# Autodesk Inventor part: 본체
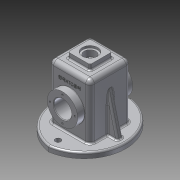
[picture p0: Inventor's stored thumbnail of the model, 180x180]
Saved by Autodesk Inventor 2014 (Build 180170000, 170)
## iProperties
Created: 2017-07
Part Number: 본체
Material: 알루미늄 6061
Document SubType Name: Modeling
Designer: user
Mass: 925.928 g
Surface Area: 965.8 cm^2
Volume: 341.671 cm^3
Density: 2.71 g/cm^3
Appearance: 알루미늄 - 평지
Author: user
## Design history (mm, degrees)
sketch "스케치1"
  geometry: L1 (-37, -37)-(37, -37); L2 (37, -37)-(37, 37); L3 (37, 37)-(-37, 37); L4 (-37, 37)-(-37, -37); L5 (-37, -37)-(37, 37); L6 (37, -37)-(-37, 37); 1 further point
  constraints: 12 end point, 2 midpoint, 2 parallel, 1 horizontal, 1 perpendicular
  dimensions: "d0" = 74 distance of L1.start L1.end; "d1" = 74 distance of L1.end L2.end
extrude "돌출1" new body sketch "스케치1" stored distance "d2" = 90; taper "d3" = 0 deg
node "작업 평면1"
sketch "스케치2"
  geometry: L1 (-75, -65)-(75, -65); L2 (75, -65)-(75, 65); L3 (75, 65)-(-75, 65); L4 (-75, 65)-(-75, -65); L5 (-75, -65)-(75, 65); L6 (75, -65)-(-75, 65); 1 further point
  constraints: 12 end point, 2 midpoint, 2 parallel, 1 horizontal, 1 perpendicular
  dimensions: "d5" = 150 distance of L2.end L3.end; "d6" = 130 distance of L3.end L1.start
extrude "돌출2" join sketch "스케치2" stored distance "d7" = 90; taper "d8" = 0 deg
sketch "스케치5"
  geometry: L1 (0, 0)-(0, 130) reference; L2 (150, 0)-(0, 0) reference; L3 (150, 130)-(150, 0) reference; L4 (0, 130)-(150, 130) reference; L5 (0, 130)-(0, 0) reference; L6 (0, 65)-(150, 65); A1 r 75.769 centre (75, 54.231) between (150, 65) and (0, 65); A2 r 75.769 centre (75, 75.769) between (0, 65) and (150, 65); 1 further point
  constraints: 4 point on circle, 2 centre point, 2 end point, 2 midpoint, 1 perpendicular, 1 symmetric about line, 1 other
  dimensions: "d29" = 130 distance of L1.start L1.end (derived)
extrude "돌출5" cut sketch "스케치5" stored distance "d15" = 13; taper "d16" = 0 deg
sketch "스케치7"
  geometry: 1 further point
sketch "스케치8"
  geometry: L1 (-37, -37)-(37, -37); L2 (37, -37)-(37, 37); L3 (37, 37)-(-37, 37); L4 (-37, 37)-(-37, -37); L5 (-37, -37)-(37, 37); L6 (37, -37)-(-37, 37); 1 further point
  constraints: 12 end point, 2 midpoint, 2 parallel, 1 horizontal, 1 perpendicular
extrude "돌출6" join sketch "스케치8" distance "d20" = 10; taper "d21" = 0 deg
sketch "스케치12"
  geometry: 1 further point
sketch "스케치13"
  geometry: C1 r 27.5 at (45, 37); 1 further point
  constraints: 1 centre point, 1 coincident
  dimensions: "d30" = 55 diameter of C1
extrude "돌출9" join sketch "스케치13" distance "d31" = 13; taper "d32" = 0 deg
sketch "스케치14"
  geometry: C1 r 27.5 at (-45, 37); 1 further point
  constraints: 1 centre point, 1 coincident
  dimensions: "d33" = 55 diameter of C1
extrude "돌출10" join sketch "스케치14" distance "d34" = 13; taper "d35" = 0 deg
sketch "스케치15"
  geometry: L1 (65, -45)-(-65, -45) reference; L2 (-65, -45)-(-55, -45); L3 (0, -45)-(-65, -45) reference; L4 (-65, -45)-(-65, 69.043); L5 (-55, -45)-(-32.5, 45.243); L6 (-55, -45)-(-32.5, -45); L7 (-32.5, -45)-(-55, -45); L8 (-55, -45)-(-32.5, -45); L9 (-37, 55)-(-37, -45) reference; L10 (37, 55)-(-37, 55) reference; L11 (37, -45)-(37, 55) reference; L12 (-37, -45)-(37, -45) reference; L13 (-32.5, 45.243)-(-32.5, -45); L14 (-37, 55)-(-37, -45) reference; L15 (-32.5, -45)-(-55, -45); C1 r 27.5 at (0, 0) reference; 1 further point
  constraints: 16 end point, 4 collinear, 1 midpoint, 1 parallel, 1 perpendicular, 1 point on line
  dimensions: "d36" = 10 distance of L1.end L2.end; "d37" = 14 deg angle of L5 L4
  node "투영된 루프1"
sketch "스케치16"
  geometry: 1 further point
extrude "돌출11" join sketch "스케치15" stored distance "d38" = 10; taper "d39" = 0 deg
sketch "스케치17"
  geometry: L1 (-20, -20)-(20, -20); L2 (20, -20)-(20, 20); L3 (20, 20)-(-20, 20); L4 (-20, 20)-(-20, -20); L5 (-20, -20)-(20, 20); L6 (20, -20)-(-20, 20); 1 further point
  constraints: 12 end point, 2 midpoint, 2 parallel, 1 horizontal, 1 perpendicular
  dimensions: "d40" = 40 distance of L3.end L2.end; "d41" = 40 distance of L2.end L1.end
extrude "돌출12" join sketch "스케치17" distance "d42" = 10; taper "d43" = 0 deg
sketch "스케치18"
  geometry: L1 (-50, 27.5)-(-50, -27.5) reference; L2 (-50, 0)-(50, 0); L3 (50, -27.5)-(50, 27.5) reference; L4 (-50, 0)-(-50, 16); L5 (-50, 16)-(-25, 16); L6 (-37, -45)-(-37, 55) reference; L7 (-25, 16)-(-25, 20.5); L8 (-25, 20.5)-(-32, 27.5); L9 (-32, 27.5)-(-32, 50); L10 (-32, 50)-(32, 50); L11 (32, 50)-(32, 27.5); L12 (32, 27.5)-(25, 20.5); L13 (25, 20.5)-(25, 16); L14 (25, 16)-(50, 16); L15 (37, 55)-(-37, 55) reference; L16 (0, 50)-(0, -55); L17 (-75, -55)-(75, -55) reference; L18 (-32, -27.5)-(-32, -50); L19 (-25, -20.5)-(-32, -27.5); L20 (32, -50)-(32, -27.5); L21 (32, -27.5)-(25, -20.5); L22 (25, -20.5)-(25, -16); L23 (25, -16)-(50, -16); L24 (-50, -16)-(-25, -16); L25 (-50, -27.5)-(-50, 27.5); L26 (-25, -20.5)-(-25, -16); L27 (32, -50)-(32, -55); L28 (-32, -50)-(-32, -55); L29 (-25, 16)-(-25, -16); L30 (25, 16)-(25, -16); L31 (-32, -55)-(32, -55); L32 (50, 16)-(50, -16); 1 further point
  constraints: 54 end point, 12 symmetric about line, 7 parallel, 7 perpendicular, 5 point on line, 4 midpoint, 1 collinear
  dimensions: "d44" = 16 distance of L2.start L4.end; "d45" = 5 distance between parallel lines of L10 L15; "d46" = 7 distance between parallel lines of L11 L13; "d47" = 7 distance between parallel lines of L9 L7; "d48" = 55 diameter of L8.end L2; "d49" = 55 diameter of L11.end L2; "d50" = 32 diameter of L14 L2; "d51" = 135 deg angle of L9 L8; "d52" = 135 deg angle of L11 L12 (derived); "d53" = 64 distance of L9.end L10.end; "d54" = 25 distance of L4.end L5.end
extrude "돌출13" cut sketch "스케치18" stored distance "d55" = 64; taper "d56" = 0 deg
sketch "스케치19"
  geometry: C1 r 27.5 at (0, 0) reference; C2 r 16 at (0, 0)
  constraints: 1 centre point, 1 coincident
  dimensions: "d57" = 32 diameter of C2
extrude "돌출14" cut sketch "스케치19" stored distance "d58" = 64; taper "d59" = 0 deg
sketch "스케치20"
  geometry: C1 r 14 at (0, 0); 1 further point
  constraints: 1 centre point, 1 coincident
  dimensions: "d60" = 28 diameter of C1
extrude "돌출15" cut sketch "스케치20" distance "d61" = 4; taper "d62" = 0 deg
sketch "스케치21"
  geometry: C1 r 14 at (0, 0) reference; C2 r 10.5 at (0, 0)
  constraints: 1 centre point, 1 coincident
  dimensions: "d63" = 21 diameter of C2
extrude "돌출16" cut sketch "스케치21" stored distance "d64" = 4; taper "d65" = 0 deg
sketch "스케치22"
  geometry: L1 (-5, 44.231)-(5, 44.231) reference; L2 (0, -10.769)-(0, 32.025); C1 r 5 at (58, -10.769); C2 r 5 at (-58, -10.769); A1 r 75.769 centre (0, -21.538) between (75, -10.769) and (-75, -10.769) reference; 1 further point
  constraints: 2 centre point, 2 end point, 1 perpendicular, 1 point on circle, 1 symmetric about line, 1 other
  dimensions: "d66" = 10 diameter of C1; "d68" = 58 distance of L2.start C1.centre
extrude "돌출17" cut sketch "스케치22" stored distance "d69" = 4; taper "d70" = 0 deg
sketch "스케치23" dims "d71" = 45
  geometry: C1 r 27.5 at (0, 0) reference; 2 further points
  constraints: 1 coincident, 1 horizontal alignment, 2 other
hole "구멍1" sketch "스케치23" at (-22.5, 0) diameter "d72" = 3.242; stored, may be unused: countersink angle "d76" = 90 deg, drill point angle "d78" = 118 deg; dims "d73" = 8, "d74" = 4, "d75" = 2, "d77" = 10
fillet "모깎기1" dims "d82" = 8
fillet "모깎기2" dims "d83" = 8
fillet "모깎기3" dims "d84" = 3
fillet "모깎기4" dims "d85" = 3
fillet "모깎기5" dims "d86" = 3
fillet "모깎기6" dims "d87" = 3
fillet "모깎기7" dims "d88" = 3
fillet "모깎기8" dims "d89" = 3
fillet "모깎기9" dims "d90" = 3
fillet "모깎기10" dims "d91" = 3
fillet "모깎기11" dims "d92" = 3
chamfer "모따기1" distance "d93" = 1; stored, may be unused: second distance "d94" = 2, angle "d95" = 45 deg
chamfer "모따기2" distance "d96" = 1; stored, may be unused: second distance "d97" = 2, angle "d98" = 45 deg
fillet "모깎기12" dims "d99" = 0.5
node "작업 평면2"
sketch "스케치25"
  geometry: L1 (89, 66)-(0, 66) reference; L2 (-18, 12)-(-18, 46) reference; 2 further points
  constraints: 1 other
  dimensions: "d103" = 37 distance from line of L1 point (12, 29); "d104" = 30 distance from line of L2 point (12, 29)
feature "엠보싱1" sketch "스케치25" dims "d105" = 0.5, "d106" = 0
fillet "모깎기13" dims "d107" = 4
fillet "모깎기14" dims "d108" = 5.77
fillet "모깎기15" dims "d109" = 5.12
fillet "모깎기16" dims "d110" = 4.4
node "솔리드1"
mirror "대칭1"
pattern_circular "원형 패턴1" dims angle "d80" = 360 deg
mirror "대칭2"
mirror "대칭3"
other parameters: "d4" = -55, "d102" = 5
